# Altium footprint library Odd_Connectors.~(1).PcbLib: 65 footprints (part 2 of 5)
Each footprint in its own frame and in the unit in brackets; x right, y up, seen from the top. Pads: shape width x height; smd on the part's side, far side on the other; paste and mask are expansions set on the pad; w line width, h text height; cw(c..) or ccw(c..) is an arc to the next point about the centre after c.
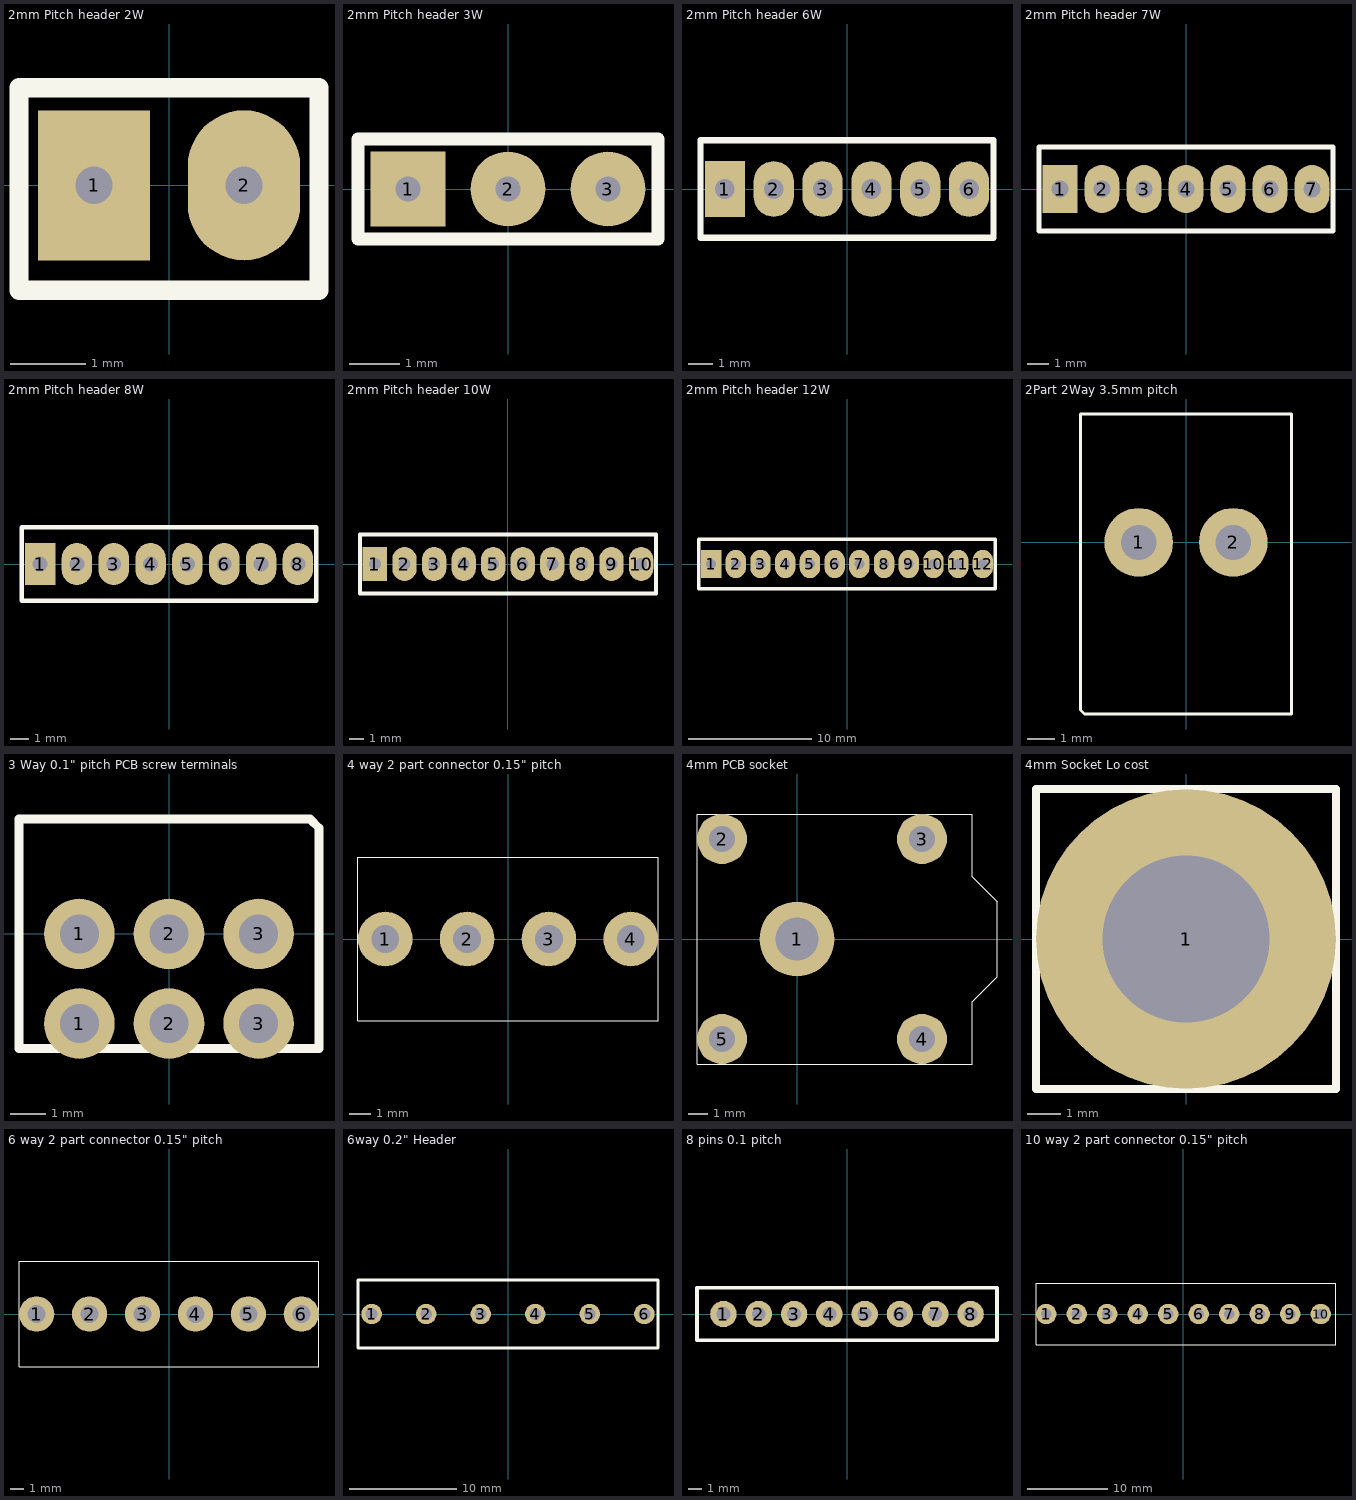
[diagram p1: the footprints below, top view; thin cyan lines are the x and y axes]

## 2mm Pitch header 2W [mm] "2mm pitch single row 12W"
height 5
pads (2):
  rect 1.5x2 hole 0.5: 1(-1,0)
  oval 1.5x2 hole 0.5: 2(1,0)
Top Overlay:
  lines w0.254: -2,-1.4 2,-1.4 2,1.3 -2,1.3 -2,-1.4

## 2mm Pitch header 3W [mm] "2mm pitch single row 3W"
height 5
pads (3):
  rect 1.5x1.5 hole 0.5: 1(-2,0)
  round 1.5 hole 0.5: 2(0,0) 3(2,0)
Top Overlay:
  lines w0.254: -3,-1 -3,1 3,1 3,-1 -3,-1

## 2mm Pitch header 6W [mil] "2mm pitch single row 6W"
height 196.85
pads (6):
  rect 65x90 hole 31.5: 1(-196.85,0)
  oval 65x90 hole 31.5: 2(-118.11,0) 3(-39.37,0) 4(39.37,0) 5(118.11,0) 6(196.85,0)
Top Overlay:
  lines w10: -236.22,-78.74 236.22,-78.74 236.22,78.74 -236.22,78.74 -236.22,0 -236.22,-78.74

## 2mm Pitch header 7W [mil] "2mm pitch single row 7W"
height 196.85
pads (7):
  rect 65x90 hole 31.5: 1(-236.22,0)
  oval 65x90 hole 31.5: 2(-157.48,0) 3(-78.74,0) 4(0,0) 5(78.74,0) 6(157.48,0) 7(236.22,0)
Top Overlay:
  lines w10: -275.59,-78.74 -275.59,0 -275.59,78.74 275.59,78.74 275.59,-78.74 -275.59,-78.74

## 2mm Pitch header 8W [mil] "2mm pitch single row 8W"
height 196.85
pads (8):
  rect 65x90 hole 31.5: 1(-275.59,0)
  oval 65x90 hole 31.5: 2(-196.85,0) 3(-118.11,0) 4(-39.37,0) 5(39.37,0) 6(118.11,0) 7(196.85,0) 8(275.59,0)
Top Overlay:
  lines w10: -314.96,-78.74 314.96,-78.74 314.96,78.74 -314.96,78.74 -314.96,0 -314.96,-78.74

## 2mm Pitch header 10W [mil] "2mm pitch single row 10W"
height 196.85
pads (10):
  rect 65x90 hole 31.5: 1(-354.33,0)
  oval 65x90 hole 31.5: 2(-275.59,0) 3(-196.85,0) 4(-118.11,0) 5(-39.37,0) 6(39.37,0) 7(118.11,0) 8(196.85,0) 9(275.59,0) 10(354.33,0)
Top Overlay:
  lines w10: -393.7,-78.74 -393.7,0 -393.7,78.74 393.7,78.74 393.7,-78.74 -393.7,-78.74

## 2mm Pitch header 12W [mil] "2mm pitch single row 12W"
height 196.85
pads (12):
  rect 65x90 hole 31.5: 1(-433.07,0)
  oval 65x90 hole 31.5: 2(-354.33,0) 3(-275.59,0) 4(-196.85,0) 5(-118.11,0) 6(-39.37,0) 7(39.37,0) 8(118.11,0) 9(196.85,0) 10(275.59,0) 11(354.33,0) 12(433.07,0)
Top Overlay:
  lines w10: -472.44,-78.74 -472.44,0 -472.44,78.74 472.44,78.74 472.44,-78.74 -472.44,-78.74

## 2Part 2Way 3.5mm pitch [mm] "2Part 2Way 3.5mm pitch such as IMO 20.155/MV/02 + M/02"
height 15
pads (2):
  round 2.54 hole 1.3: 1(-1.75,0) 2(1.75,0)
Top Overlay:
  lines w0.1: -3.9,-6.2 -3.9,4.75 3.9,4.75 3.9,-6.35 -3.75,-6.35 -3.9,-6.2

## 3 Way 0.1" pitch PCB screw terminals [mm]
height 8.5
pads (6):
  round 2 hole 1.1: 1(-2.54,-2.54) 1(-2.54,0) 2(0,-2.54) 2(0,0) 3(2.54,-2.54) 3(2.54,0)
Top Overlay:
  lines w0.254: -4.25,-3.25 -4.25,3.25 4,3.25 4.25,3 4.25,-3.25 -4.25,-3.25

## 4 way 2 part connector 0.15" pitch [mm] "4 way connector or terminal block - 0.15\" pitch"
height 10.16
pads (4):
  round 2.54 hole 1.3 unplated: 1(-5.715,0) 2(-1.905,0) 3(1.905,0) 4(5.715,0)
Top Overlay:
  lines w0.025: -6.985,-3.81 6.985,-3.81 6.985,3.81 -6.985,3.81 -6.985,-3.81

## 4mm PCB socket [mm] "Gold plated PCB 4mm socket"
height 11.5
pads (5):
  round 3.81 hole 2.2 unplated: 1(0,0)
  round 2.54 hole 1.3 unplated: 2(-3.81,5.08) 3(6.35,5.08) 4(6.35,-5.08) 5(-3.81,-5.08)
Top Overlay:
  lines w0.025: -5.08,-6.35 8.89,-6.35 8.89,-3.175 10.16,-1.905 10.16,1.905 8.89,3.175 8.89,6.35 -5.08,6.35 -5.08,-6.35

## 4mm Socket Lo cost [mm] "Low cost 4mm socket"
pads (1):
  round 9 hole 5: 1(0,0)
Top Overlay:
  lines w0.254: -4.5,-4.5 4.5,-4.5 4.5,4.5 -4.5,4.5 -4.5,-4.5

## 6 way 2 part connector 0.15" pitch [mm] "6 way connector or terminal block - 0.15\" pitch"
height 10.16
pads (6):
  round 2.54 hole 1.3 unplated: 1(-9.525,0) 2(-5.715,0) 3(-1.905,0) 4(1.905,0) 5(5.715,0) 6(9.525,0)
Top Overlay:
  lines w0.025: -10.795,-3.81 -10.795,3.81 10.795,3.81 10.795,-3.81 -10.795,-3.81

## 6way 0.2" Header [mm] "Header with big gaps between the pins!"
pads (6):
  round 1.905 hole 1.1: 1(-12.7,0) 2(-7.62,0) 3(-2.54,0) 4(2.54,0) 5(7.62,0) 6(12.7,0)
Top Overlay:
  lines w0.254: -13.97,-3.175 13.97,-3.175 13.97,3.175 -13.97,3.175 -13.97,-3.175

## 8 pins 0.1 pitch [mm] "pin header"
height 12
pads (8):
  round 1.905 hole 1: 1(-8.89,0) 2(-6.35,0) 3(-3.81,0) 4(-1.27,0) 5(1.27,0) 6(3.81,0) 7(6.35,0) 8(8.89,0)
Top Overlay:
  lines w0.254: -10.795,-1.905 -10.795,1.905 10.795,1.905 10.795,-1.905 -10.795,-1.905

## 10 way 2 part connector 0.15" pitch [mm] "10 way connector or terminal block - 0.15\" pitch"
height 10.16
pads (10):
  round 2.54 hole 1.3 unplated: 1(-17.145,0) 2(-13.335,0) 3(-9.525,0) 4(-5.715,0) 5(-1.905,0) 6(1.905,0) 7(5.715,0) 8(9.525,0) 9(13.335,0) 10(17.145,0)
Top Overlay:
  lines w0.025: -18.415,-3.81 19.05,-3.81 19.05,3.81 -18.415,3.81 -18.415,-3.81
